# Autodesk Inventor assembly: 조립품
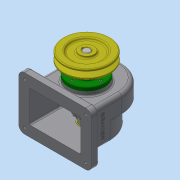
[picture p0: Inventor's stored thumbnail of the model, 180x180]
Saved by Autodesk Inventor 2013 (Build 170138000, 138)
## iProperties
Created: 2017-11
Part Number: 조립품
Document SubType Name: Assembly
Designer: dgall
Author: dgall
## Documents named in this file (14)
- C:\Users\dgall\Desktop\471107V1033\조립품.iam
- C:\Users\dgall\Desktop\471107V1033\본체.ipt
- C:\Users\dgall\Desktop\471107V1033\앞커버.ipt
- C:\Users\dgall\Desktop\471107V1033\뒤커버.ipt
- C:\Users\dgall\Desktop\471107V1033\볼트 M3 x 8.ipt
- C:\Users\dgall\Desktop\471107V1033\축.ipt
- C:\Users\dgall\Desktop\471107V1033\키 - 5 x 5 x 18.ipt
- C:\Users\dgall\Desktop\471107V1033\키 - 6 x 6 x 22.ipt
- C:\Users\dgall\Desktop\471107V1033\스퍼기어.ipt
- C:\Users\dgall\Desktop\471107V1033\베어링 6002.ipt
- C:\Users\dgall\Desktop\471107V1033\V-벨트풀리.ipt
- C:\Users\dgall\Desktop\471107V1033\멈춤나사 - M4 x 10.ipt
- 멈춤나사 - M4 x 10.ipt
- C:\Users\dgall\Desktop\471107V1033\오일 실 15 30 7.ipt
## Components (1 placed, 1 different names)
1. V-벨트풀리:1
